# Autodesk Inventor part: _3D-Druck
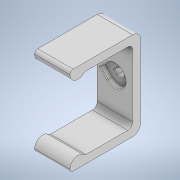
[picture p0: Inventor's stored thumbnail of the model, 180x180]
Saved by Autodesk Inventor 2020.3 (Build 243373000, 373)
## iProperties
Created: 2020-11
Part Number: _3D-Druck
Material: Generisch
Document SubType Name: Modeling
Designer: Philipp
Density: 1 g/cm^3
Appearance: Vorgabe
Author: Philipp
Part Number: Warndreieck Halter
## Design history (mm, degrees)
sketch "Skizze1"
  geometry: L1 (0, -0.899)-(0, -27); L2 (3, -30)-(42, -30); L3 (45, -27)-(45, -0.899); L4 (50, 7)-(50, -30); L5 (45, -35)-(0, -35); L6 (-5, -30)-(-5, 7); A1 r 5 centre (48, 4) between (48, 9) and (44.429, 0.501); A2 r 5 centre (-3, 4) between (0.571, 0.501) and (-3, 9); A3 r 3 centre (42, -27) between (42, -30) and (45, -27); A4 r 3 centre (3, -27) between (0, -27) and (3, -30); A5 r 5 centre (45, -30) between (45, -35) and (50, -30); A6 r 5 centre (0, -30) between (-5, -30) and (0, -35); A7 r 2 centre (48, 7) between (50, 7) and (48, 9); A8 r 2 centre (-3, 7) between (-3, 9) and (-5, 7); A9 r 2 centre (43, -0.899) between (45, -0.899) and (44.429, 0.501); A10 r 2 centre (2, -0.899) between (0.571, 0.501) and (0, -0.899); 6 further points
  constraints: 24 point on circle, 16 tangent, 12 end point, 10 centre point, 8 point on line, 5 equal radius, 4 perpendicular, 2 vertical
  dimensions: "d0" = 30 distance of point (0, 0) point (0, -30); "d1" = 45 distance of point (0, -30) point (45, -30); "d2" = 10 diameter of A1; "d3" = 10 diameter of A2; "d4" = 48 horizontal distance of point (0, 0) A1.centre; "d5" = 3 horizontal distance of point (0, 0) A2.centre; "d6" = 4 vertical distance of point (0, 0) A1.centre; "d7" = 5 distance between parallel lines of L2 L5; "d8" = 5 distance between parallel lines of L6 L1; "d9" = 5 distance between parallel lines of L4 L3; "d10" = 3 radius of A3; "d11" = 5 radius of A5; "d12" = 2 radius of A7 (derived)
extrude "Extrusion1" new body sketch "Skizze1" distance "d13" = 22; taper "d14" = 0 deg
sketch "Skizze2"
  geometry: L1 (0, 0)-(0, 45) reference; L2 (0, 50)-(-22, 50) reference; L3 (-10, 17.092)-(-10, 15.092); L4 (-10, 15.092)-(-12, 15.092); L5 (-12, 15.092)-(-12, 17.092); L6 (-22, 0)-(-22, 45) reference; A1 r 5.5 centre (-11, 22.5) between (-10, 17.092) and (-12, 17.092)
  constraints: 6 end point, 2 perpendicular, 2 point on circle, 1 centre point, 1 vertical
  dimensions: "d15" = 11 diameter of A1; "d16" = 11 distance from line of A1.centre L1; "d17" = 27.5 distance from line of L2 A1.centre; "d39" = 2 distance of L3.start L3.end; "d40" = 2 distance between parallel lines of L5 L3; "d41" = 10 distance between parallel lines of L6 L5
extrude "Extrusion2" join sketch "Skizze2" distance "d18" = 3; taper "d19" = 0 deg
sketch "Skizze3"
  geometry: L1 (9.232, 21.268)-(7.464, 19.5); L2 (7.464, 19.5)-(9.232, 17.732); L3 (6.404, 24.096)-(1.808, 19.5); L4 (1.808, 19.5)-(6.404, 14.904); L5 (22, 39)-(22, 0) reference; L6 (0, 47)-(22, 47) reference; A1 r 2.5 centre (11, 19.5) between (9.232, 17.732) and (9.232, 21.268); A2 r 6.5 centre (11, 19.5) between (6.404, 14.904) and (6.404, 24.096); 3 further points
  constraints: 8 end point, 4 point on circle, 4 tangent, 2 centre point, 2 coincident, 1 concentric
  dimensions: "d22" = 5 diameter of A1; "d25" = 90 deg angle of L2 L1; "d26" = 0 vertical distance of point (11, 19.5) L1.end; "d27" = 90 deg angle of L4 L3; "d28" = 0 vertical distance of point (11, 19.5) L3.end; "d35" = 11 distance from line of L5 A1.centre; "d37" = 27.5 distance from line of L6 point (11, 19.5); "d38" = 6.5 radius of A2
extrude "Extrusion3" cut sketch "Skizze3" distance "d20" = 3; taper "d21" = 0 deg
extrude "Extrusion4" cut sketch "Skizze3" extent not by distance; stored distance "d23" = 39; taper "d24" = 0 deg
chamfer "Fase3" distance "d42" = 0.5; stored, may be unused: second distance "d43" = 2, angle "d44" = 45 deg
node "Volumenkörper1"
